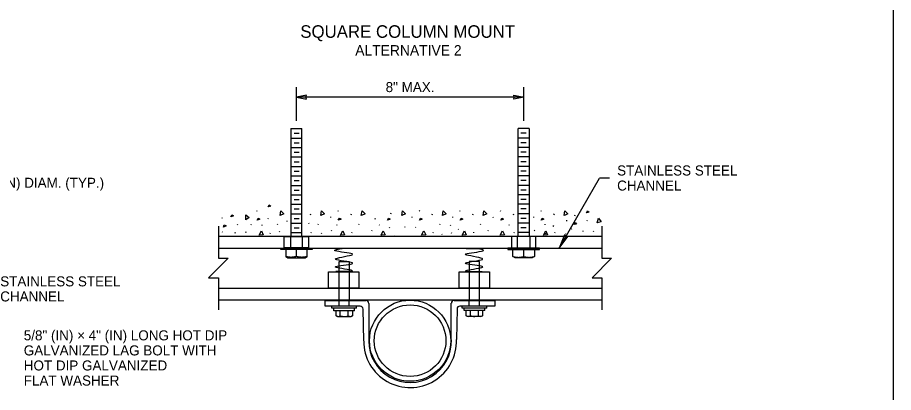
# Model space of a CAD drawing. Extents: x 99862 to 103680, y 99470 to 102076.
# Drawn here: x 101757 to 103151, y 100628 to 101226 of the extents above; entities that cross this region are included whole.
import ezdxf

# ---------------------------------------------------------------- set-up
doc = ezdxf.new("R2010")
doc.units = 0
for name, color, linetype in [('Level 1', 7, 'Continuous'), ('Level 10', 7, 'Continuous'), ('Level 11', 7, 'Continuous'), ('Level 15', 7, 'Continuous'), ('Level 2', 7, 'Continuous'), ('Level 20', 7, 'Continuous'), ('Level 3', 7, 'Continuous'), ('Level 4', 7, 'Continuous'), ('Level 5', 7, 'Continuous'), ('Level 6', 7, 'Continuous'), ('Level 7', 7, 'Continuous'), ('Level 8', 7, 'Continuous'), ('Level 9', 7, 'Continuous')]:
    doc.layers.add(name, color=color, linetype=linetype)

msp = doc.modelspace()

# ---------------------------------------------------------------- linework, layer by layer
at = {"layer": 'Level 1'}
for p, q in [((102076.6, 100858.3), (102686.8, 100858.3)), ((102076.6, 100794.5), (102686.8, 100794.5)), ((102076.6, 100776.1), (102687, 100776.1))]:
    msp.add_line(p, q, dxfattribs=at)
msp.add_lwpolyline([(99862, 99999.5), (103151, 99999.5), (103151, 102075.5), (99862, 102075.5)], close=True, dxfattribs=at)
at = {"layer": 'Level 10'}
msp.add_line((102076.6, 100877.3), (102686.9, 100877.3), dxfattribs=at)
at = {"layer": 'Level 11'}
for p, q in [((102138, 100917), (102138.5, 100918.2)), ((102267.2, 100917), (102267.7, 100918.2)), ((102396.4, 100917), (102397, 100918.2)), ((102461, 100917), (102461.6, 100918.2)), ((102525.6, 100917), (102526.2, 100918.2)), ((102590.2, 100917), (102590.8, 100918.2)), ((102082.6, 100905.8), (102083, 100907)), ((102155.9, 100905), (102156.5, 100906.2)), ((102223.1, 100911.5), (102223.6, 100912.7)), ((102255.2, 100908.1), (102255.3, 100906.9)), ((102287.7, 100911.5), (102288.2, 100912.7)), ((102326.2, 100904.6), (102326.7, 100905.8)), ((102351, 100913.1), (102351.5, 100914.3)), ((102384.4, 100908.1), (102384.5, 100906.9)), ((102416.9, 100911.5), (102417.5, 100912.7)), ((102449, 100908.1), (102449.1, 100906.9)), ((102481.5, 100911.5), (102482.1, 100912.7)), ((102513.6, 100908.1), (102513.7, 100906.9)), ((102546.1, 100911.5), (102546.7, 100912.7)), ((102578.2, 100908.1), (102578.3, 100906.9)), ((102610.7, 100911.5), (102611.3, 100912.7)), ((102630.7, 100902.6), (102630.7, 100901.4)), ((102643.7, 100910), (102644.4, 100911.1)), ((102663.4, 100901.9), (102664.1, 100903)), ((102106.9, 100895.5), (102107.3, 100896.7)), ((102128.8, 100895.3), (102129.3, 100896.5)), ((102145.6, 100895.4), (102145.7, 100894.2)), ((102170.8, 100895.8), (102171.3, 100897)), ((102185.5, 100901.7), (102185.6, 100900.5)), ((102220.1, 100898.4), (102220.7, 100897.6)), ((102235.4, 100895.8), (102235.9, 100897)), ((102264.4, 100895.8), (102264.9, 100895)), ((102300, 100895.8), (102300.5, 100897)), ((102332.6, 100895.5), (102333.1, 100894.7)), ((102348.8, 100890.4), (102349.3, 100891.6)), ((102373.4, 100891.8), (102373.9, 100893)), ((102390.5, 100891.8), (102391, 100891)), ((102429.2, 100895.8), (102429.7, 100897)), ((102446.1, 100894.2), (102446.7, 100895.4)), ((102458.2, 100888.7), (102458.7, 100887.9)), ((102493.8, 100895.8), (102494.3, 100897)), ((102538.8, 100895.8), (102539.4, 100895)), ((102596.1, 100896.7), (102596.1, 100895.4)), ((102609.5, 100893), (102610.2, 100894.1)), ((102638.3, 100889.3), (102638.7, 100888.4)), ((102082.4, 100884.4), (102083.1, 100883.7)), ((102103.4, 100882.2), (102103.8, 100883.5)), ((102120.4, 100883.4), (102120.8, 100884.7)), ((102158.9, 100881.5), (102159.3, 100882.7)), ((102173.9, 100884.3), (102174.5, 100885.5)), ((102224.5, 100882.7), (102225, 100883.9)), ((102240.3, 100882.5), (102240.8, 100881.7)), ((102256.4, 100885.8), (102257, 100887)), ((102289.1, 100882.7), (102289.6, 100883.9)), ((102321, 100885.8), (102321.6, 100887)), ((102357.4, 100877.1), (102358, 100878.3)), ((102418.3, 100882.7), (102418.8, 100883.9)), ((102432.2, 100880.6), (102432.7, 100879.8)), ((102447.4, 100882.1), (102447.9, 100883.3)), ((102482.9, 100882.7), (102483.4, 100883.9)), ((102506.2, 100885.8), (102506.7, 100887)), ((102547.5, 100882.7), (102548, 100883.9)), ((102579.4, 100885.8), (102580, 100887)), ((102597, 100881.3), (102597.7, 100882.5)), ((102612.1, 100882.7), (102612.6, 100883.9)), ((102629.1, 100880.4), (102629.8, 100881.5)), ((102656.7, 100886), (102656.7, 100884.7)), ((102673.6, 100884.8), (102674.3, 100886))]:
    msp.add_line(p, q, dxfattribs=at)
for points in [[(102155.8, 100923.9), (102157.4, 100927.3), (102160.1, 100925.3), (102155.8, 100923.9)], [(102174.9, 100910.1), (102176, 100917.8), (102180.8, 100912.8), (102175, 100910.1)], [(102239.5, 100910.1), (102240.6, 100917.8), (102245.4, 100912.8), (102239.6, 100910.1)], [(102304.1, 100910.1), (102305.2, 100917.8), (102310, 100912.8), (102304.2, 100910.1)], [(102368.7, 100910.1), (102369.8, 100917.8), (102374.6, 100912.8), (102368.8, 100910.1)], [(102433.3, 100910.1), (102434.4, 100917.8), (102439.2, 100912.8), (102433.4, 100910.1)], [(102497.9, 100910.1), (102499, 100917.8), (102503.8, 100912.8), (102498.1, 100910.1)], [(102627.1, 100910.1), (102628.2, 100917.8), (102633, 100912.8), (102627.3, 100910.1)], [(102662.3, 100914.6), (102664.3, 100917.8), (102666.8, 100915.4), (102662.3, 100914.6)], [(102096.6, 100907.9), (102097.8, 100911.4), (102100.7, 100909.8), (102096.6, 100907.9)], [(102120.1, 100903.4), (102120.2, 100911.2), (102125.6, 100906.9), (102120.2, 100903.5)], [(102138.3, 100902.8), (102139.9, 100906.2), (102142.6, 100904.2), (102138.3, 100902.8)], [(102267.5, 100902.8), (102269.1, 100906.2), (102271.8, 100904.2), (102267.5, 100902.8)], [(102345.5, 100902.8), (102347.1, 100906.2), (102349.8, 100904.2), (102345.5, 100902.8)], [(102396.7, 100902.8), (102398.3, 100906.2), (102401, 100904.2), (102396.7, 100902.8)], [(102461.3, 100902.8), (102462.9, 100906.2), (102465.6, 100904.2), (102461.3, 100902.8)], [(102525.9, 100902.8), (102527.5, 100906.2), (102530.2, 100904.2), (102525.9, 100902.8)], [(102590.5, 100902.8), (102592.1, 100906.2), (102594.8, 100904.2), (102590.5, 100902.8)], [(102679.5, 100898.5), (102681.5, 100906), (102685.7, 100900.4), (102679.6, 100898.5)], [(102084.6, 100891.7), (102085.8, 100895.3), (102088.8, 100893.6), (102084.6, 100891.7)], [(102642.2, 100895.9), (102644.3, 100899), (102646.7, 100896.7), (102642.2, 100895.9)], [(102141.6, 100879.1), (102145.3, 100886), (102148.1, 100879.6), (102141.8, 100879.1)], [(102270.8, 100879.1), (102274.5, 100886), (102277.3, 100879.6), (102271, 100879.1)], [(102335.5, 100879.1), (102339.1, 100886), (102341.9, 100879.6), (102335.6, 100879.1)], [(102400.1, 100879.1), (102403.7, 100886), (102406.5, 100879.6), (102400.2, 100879.1)], [(102464.7, 100879.1), (102468.3, 100886), (102471.1, 100879.6), (102464.8, 100879.1)], [(102525.3, 100879.1), (102528.9, 100886), (102531.8, 100879.6), (102525.4, 100879.1)], [(102593.9, 100879.1), (102597.5, 100886), (102600.3, 100879.6), (102594, 100879.1)]]:
    msp.add_lwpolyline(points, dxfattribs=at)
at = {"layer": 'Level 15'}
for p, q in [((102200.8, 101060.9), (102200.8, 101114.9)), ((102562.5, 101060.9), (102562.5, 101114.9)), ((102562.5, 101098.9), (102200.8, 101098.9)), ((102618.7, 100858.3), (102683.2, 100970)), ((102699.2, 100970), (102683.2, 100970))]:
    msp.add_line(p, q, dxfattribs=at)
for points in [[(102200.8, 101098.9), (102216.6, 101095.8), (102215.8, 101098.9), (102216.6, 101101.9)], [(102562.5, 101098.9), (102546.8, 101095.8), (102547.5, 101098.9), (102546.8, 101101.9)], [(102618.7, 100858.3), (102632.7, 100876.6), (102629.6, 100877.2), (102627.6, 100879.6)]]:
    msp.add_lwpolyline(points, close=True, dxfattribs=at)
for points in [[(102076.6, 100893.3), (102076.6, 100842.2), (102092, 100842.2), (102061.1, 100811.2), (102076.6, 100811.2), (102076.6, 100760.1)], [(102686.9, 100893.3), (102686.9, 100842.2), (102702.4, 100842.2), (102671.4, 100811.2), (102686.9, 100811.2), (102686.9, 100760.1)]]:
    msp.add_lwpolyline(points, dxfattribs=at)
at = {"layer": 'Level 2'}
for p, q in [((102246.7, 100765.7), (102246.7, 100774.9)), ((102246.7, 100774.9), (102311.4, 100774.9)), ((102302.2, 100765.7), (102246.7, 100765.7)), ((102268.9, 100765.7), (102268.9, 100774.9)), ((102285, 100765.7), (102285, 100774.9)), ((102316, 100770.3), (102316, 100710.2)), ((102447.3, 100712.3), (102447.3, 100770.4)), ((102452, 100775), (102516.7, 100775)), ((102516.7, 100765.8), (102461.1, 100765.8)), ((102475.9, 100765.8), (102475.9, 100775)), ((102492.1, 100765.8), (102492.1, 100775)), ((102516.7, 100775), (102516.7, 100765.8)), ((102307.9, 100710.3), (102306.9, 100761.1)), ((102456.5, 100761.3), (102455.5, 100712.6))]:
    msp.add_line(p, q, dxfattribs=at)
for centre, radius, start, end in [((102302.2, 100761.1), 4.61, 1.0465, 90), ((102311.4, 100770.3), 4.61, 0, 90), ((102452, 100770.4), 4.61, 90, 180), ((102461.1, 100761.2), 4.61, 90, 178.9097), ((102381.7, 100709.9), 73.8, 179.7114, 2.078), ((102381.7, 100709.9), 65.7, 179.7114, 2.078)]:
    msp.add_arc(centre, radius, start, end, dxfattribs=at)
at = {"layer": 'Level 3'}
for points in [[(102251.6, 100820.7), (102300, 100820.7), (102300, 100794.5), (102251.6, 100794.5)], [(102459.8, 100820.7), (102508.2, 100820.7), (102508.2, 100794.5), (102459.8, 100794.5)]]:
    msp.add_lwpolyline(points, close=True, dxfattribs=at)
at = {"layer": 'Level 4'}
for p, q in [((102268.9, 100776.1), (102268.9, 100836.8)), ((102268.9, 100836.8), (102285, 100836.8)), ((102285, 100836.8), (102285, 100776.1)), ((102492.1, 100836.9), (102475.9, 100836.9)), ((102475.9, 100836.9), (102475.9, 100776.2)), ((102492.1, 100776.2), (102492.1, 100836.9)), ((102264.1, 100750.3), (102264.1, 100758.6)), ((102266.7, 100748.9), (102264.1, 100750.3)), ((102287.3, 100748.9), (102266.7, 100748.9)), ((102270.5, 100750.3), (102270.5, 100758.6)), ((102283.4, 100750.3), (102283.4, 100758.6)), ((102289.8, 100750.3), (102287.3, 100748.9)), ((102289.8, 100758.6), (102289.8, 100750.3)), ((102471.2, 100750.5), (102471.2, 100758.7)), ((102473.7, 100749.1), (102471.2, 100750.5)), ((102494.3, 100749.1), (102473.7, 100749.1)), ((102477.6, 100750.5), (102477.6, 100758.7)), ((102490.4, 100750.5), (102490.4, 100758.7)), ((102496.9, 100750.5), (102494.3, 100749.1)), ((102496.9, 100758.7), (102496.9, 100750.5))]:
    msp.add_line(p, q, dxfattribs=at)
for points in [[(102264.1, 100750.3), (102265.2, 100749.8), (102266.2, 100749.4), (102268.4, 100749.4), (102269.5, 100749.8), (102270.5, 100750.3)], [(102270.5, 100750.3), (102271.6, 100750), (102272.6, 100749.8), (102274.8, 100749.5), (102275.9, 100749.4), (102279.1, 100749.4), (102281.3, 100749.8), (102283.4, 100750.3)], [(102283.4, 100750.3), (102284.4, 100749.8), (102285.5, 100749.4), (102287.7, 100749.4), (102288.8, 100749.8), (102289.8, 100750.3)], [(102471.2, 100750.5), (102472.2, 100749.9), (102473.3, 100749.5), (102475.5, 100749.5), (102476.5, 100749.9), (102477.6, 100750.5)], [(102477.6, 100750.5), (102478.6, 100750.2), (102479.7, 100750), (102481.8, 100749.6), (102482.9, 100749.5), (102486.2, 100749.5), (102488.3, 100749.9), (102490.4, 100750.5)], [(102490.4, 100750.5), (102491.5, 100749.9), (102492.5, 100749.5), (102494.7, 100749.5), (102495.8, 100749.9), (102496.9, 100750.5)]]:
    msp.add_open_spline(points, degree=3, dxfattribs=at)
at = {"layer": 'Level 5'}
for p, q in [((102175.8, 100855.9), (102175.8, 100858)), ((102175.8, 100858), (102225.9, 100858)), ((102225.9, 100855.9), (102175.8, 100855.9)), ((102225.9, 100858), (102225.9, 100855.9)), ((102587.5, 100858), (102537.5, 100858)), ((102537.5, 100858), (102537.5, 100855.9)), ((102537.5, 100855.9), (102587.5, 100855.9)), ((102587.5, 100855.9), (102587.5, 100858)), ((102503.6, 100762.5), (102464.4, 100762.5)), ((102296.6, 100762.4), (102257.4, 100762.4))]:
    msp.add_line(p, q, dxfattribs=at)
for points in [[(102257.4, 100762.4), (102257.4, 100765.7)], [(102296.6, 100762.4), (102296.6, 100765.7)], [(102464.4, 100762.5), (102464.4, 100765.8)], [(102503.6, 100762.5), (102503.6, 100765.8)]]:
    msp.add_lwpolyline(points, dxfattribs=at)
at = {"layer": 'Level 6'}
for p, q in [((102293.4, 100758.6), (102260.6, 100758.6)), ((102500.4, 100758.7), (102467.6, 100758.7))]:
    msp.add_line(p, q, dxfattribs=at)
for points in [[(102467.6, 100758.7), (102467.6, 100762.5)], [(102500.4, 100758.7), (102500.4, 100762.5)], [(102260.6, 100758.6), (102260.6, 100762.4)], [(102293.4, 100758.6), (102293.4, 100762.4)]]:
    msp.add_lwpolyline(points, dxfattribs=at)
at = {"layer": 'Level 7'}
for p, q in [((102289, 100857.9), (102263.7, 100857.9)), ((102471.1, 100857.9), (102496.4, 100857.9)), ((102289, 100821), (102263.7, 100821)), ((102471.1, 100821), (102496.4, 100821))]:
    msp.add_line(p, q, dxfattribs=at)
for points in [[(102287.1, 100821), (102287.2, 100821), (102290.3, 100821.6), (102291, 100822.6), (102272.2, 100825.8), (102260.2, 100827.8), (102265.9, 100829.9), (102285.3, 100832.4), (102294.4, 100834.5), (102276.2, 100837.6), (102259.4, 100840.3), (102266.8, 100843.1), (102288.1, 100846.8), (102292.9, 100848.9), (102277.1, 100851.3), (102258.8, 100854.2), (102263.3, 100855.5), (102272.3, 100857.7), (102273.4, 100857.9)], [(102473.1, 100821), (102473, 100821), (102469.8, 100821.6), (102469.2, 100822.6), (102487.9, 100825.8), (102499.9, 100827.8), (102494.3, 100829.9), (102474.9, 100832.4), (102465.8, 100834.5), (102484, 100837.6), (102500.7, 100840.3), (102493.4, 100843.1), (102472.1, 100846.8), (102467.2, 100848.9), (102483.1, 100851.3), (102501.4, 100854.2), (102496.9, 100855.5), (102487.8, 100857.7), (102486.8, 100857.9)]]:
    msp.add_open_spline(points, degree=3, dxfattribs=at)
at = {"layer": 'Level 8'}
for p, q in [((102192, 101048.9), (102209.6, 101048.9)), ((102192, 101048.9), (102209.6, 101048.9)), ((102192, 101048.9), (102192, 100876.9)), ((102209.6, 100876.9), (102209.6, 101048.9)), ((102571.3, 101048.9), (102553.7, 101048.9)), ((102571.3, 101048.9), (102553.7, 101048.9)), ((102553.7, 100876.9), (102553.7, 101048.9)), ((102571.3, 101048.9), (102571.3, 100876.9)), ((102192, 101033.7), (102209.6, 101033.7)), ((102197, 101041.2), (102205.3, 101041.2)), ((102571.3, 101033.7), (102553.7, 101033.7)), ((102566.4, 101041.2), (102558.1, 101041.2)), ((102192, 101018.6), (102209.6, 101018.6)), ((102197, 101026.1), (102205.3, 101026.1)), ((102571.3, 101018.6), (102553.7, 101018.6)), ((102566.4, 101026.1), (102558.1, 101026.1)), ((102192, 101003.5), (102209.6, 101003.5)), ((102197, 101011.1), (102205.3, 101011.1)), ((102571.3, 101003.5), (102553.7, 101003.5)), ((102566.4, 101011.1), (102558.1, 101011.1)), ((102192, 100988.5), (102209.6, 100988.5)), ((102197, 100996), (102205.3, 100996)), ((102571.3, 100988.5), (102553.7, 100988.5)), ((102566.4, 100996), (102558.1, 100996)), ((102192, 100973.4), (102209.6, 100973.4)), ((102197, 100980.9), (102205.3, 100980.9)), ((102571.3, 100973.4), (102553.7, 100973.4)), ((102566.4, 100980.9), (102558.1, 100980.9)), ((102192, 100958.3), (102209.6, 100958.3)), ((102197, 100965.9), (102205.3, 100965.9)), ((102571.3, 100958.3), (102553.7, 100958.3)), ((102566.4, 100965.9), (102558.1, 100965.9)), ((102197, 100950.8), (102205.3, 100950.8)), ((102566.4, 100950.8), (102558.1, 100950.8)), ((102192, 100943.3), (102209.6, 100943.3)), ((102197, 100935.7), (102205.3, 100935.7)), ((102571.3, 100943.3), (102553.7, 100943.3)), ((102566.4, 100935.7), (102558.1, 100935.7)), ((102192, 100928.2), (102209.6, 100928.2)), ((102197, 100920.7), (102205.3, 100920.7)), ((102571.3, 100928.2), (102553.7, 100928.2)), ((102566.4, 100920.7), (102558.1, 100920.7)), ((102192, 100913.1), (102209.6, 100913.1)), ((102197, 100905.6), (102205.3, 100905.6)), ((102571.3, 100913.1), (102553.7, 100913.1)), ((102566.4, 100905.6), (102558.1, 100905.6)), ((102192, 100898.1), (102209.6, 100898.1)), ((102197, 100890.5), (102205.3, 100890.5)), ((102571.3, 100898.1), (102553.7, 100898.1)), ((102566.4, 100890.5), (102558.1, 100890.5)), ((102191.2, 100876.9), (102191.2, 100858.6)), ((102192, 100883), (102209.6, 100883)), ((102210.5, 100858.6), (102210.5, 100876.9)), ((102552.9, 100858.6), (102552.9, 100876.9)), ((102571.3, 100883), (102553.7, 100883)), ((102572.2, 100876.9), (102572.2, 100858.6)), ((102183.7, 100855.9), (102183.7, 100844.9)), ((102200.8, 100844.9), (102200.8, 100855.9)), ((102218, 100844.9), (102218, 100855.9)), ((102545.4, 100844.9), (102545.4, 100855.9)), ((102562.5, 100844.9), (102562.5, 100855.9)), ((102579.7, 100855.9), (102579.7, 100844.9)), ((102183.7, 100844.9), (102187.1, 100843)), ((102187.1, 100843), (102214.6, 100843)), ((102214.6, 100843), (102218, 100844.9)), ((102548.8, 100843), (102545.4, 100844.9)), ((102576.2, 100843), (102548.8, 100843)), ((102579.7, 100844.9), (102576.2, 100843))]:
    msp.add_line(p, q, dxfattribs=at)
for points in [[(102181.5, 100876.9), (102220.2, 100876.9), (102220.2, 100858.6), (102181.5, 100858.6)], [(102581.9, 100876.9), (102543.2, 100876.9), (102543.2, 100858.6), (102581.9, 100858.6)]]:
    msp.add_lwpolyline(points, close=True, dxfattribs=at)
for points, degree in [([(102200.8, 100844.9), (102199.4, 100844.5), (102198, 100844.2), (102195.2, 100843.7), (102193.7, 100843.6), (102190.8, 100843.6), (102189.4, 100843.7), (102186.5, 100844.2), (102185.1, 100844.5), (102183.7, 100844.9)], 3), ([(102218, 100844.9), (102216.6, 100844.5), (102215.2, 100844.2), (102212.3, 100843.7), (102210.9, 100843.6), (102208, 100843.6), (102206.5, 100843.7), (102203.7, 100844.2), (102202.2, 100844.5), (102200.8, 100844.9)], 3), ([(102200.8, 100844.9), (102200.8, 100844.9), (102200.8, 100844.9), (102200.8, 100844.9)], 2), ([(102218, 100844.9), (102218, 100844.9), (102218, 100844.9), (102218, 100844.9)], 2), ([(102545.4, 100844.9), (102545.4, 100844.9), (102545.4, 100844.9), (102545.4, 100844.9)], 2), ([(102545.4, 100844.9), (102546.8, 100844.5), (102548.2, 100844.2), (102551, 100843.7), (102552.5, 100843.6), (102555.4, 100843.6), (102556.8, 100843.7), (102559.7, 100844.2), (102561.1, 100844.5), (102562.5, 100844.9)], 3), ([(102562.5, 100844.9), (102562.5, 100844.9), (102562.5, 100844.9), (102562.5, 100844.9)], 2), ([(102562.5, 100844.9), (102563.9, 100844.5), (102565.3, 100844.2), (102568.2, 100843.7), (102569.6, 100843.6), (102572.5, 100843.6), (102574, 100843.7), (102576.8, 100844.2), (102578.3, 100844.5), (102579.7, 100844.9)], 3)]:
    msp.add_open_spline(points, degree=degree, dxfattribs=at)
at = {"layer": 'Level 9'}
for radius in [64.6, 57]:
    msp.add_circle((102381.7, 100710.8), radius, dxfattribs=at)

# ---------------------------------------------------------------- texts
at = {"layer": 'Level 20'}
for s, height, p in [('SQUARE COLUMN MOUNT', 20, (102207, 101193.4)), ('ALTERNATIVE 2', 16.5, (102294.4, 101165.2)), ('8" MAX.', 16, (102342.8, 101106.9))]:
    msp.add_text(s, height=height, dxfattribs=at).set_placement(p)
for s, p in [('STAINLESS STEEL', (102711.2, 100974)), ('3/16" (IN) DIAM. (TYP.)', (101670.8, 100954.4)), ('CHANNEL', (102711.2, 100950)), ('STAINLESS STEEL', (101729.4, 100797.3)), ('CHANNEL', (101729.4, 100773.3)), ('5/8" (IN) × 4" (IN) LONG HOT DIP', (101766.9, 100711.3)), ('GALVANIZED LAG BOLT WITH ', (101766.9, 100687.3)), ('HOT DIP GALVANIZED', (101766.9, 100663.3)), ('FLAT WASHER', (101766.9, 100639.3))]:
    msp.add_text(s, height=16, rotation=360, dxfattribs=at).set_placement(p)

doc.saveas('drawing.dxf')
